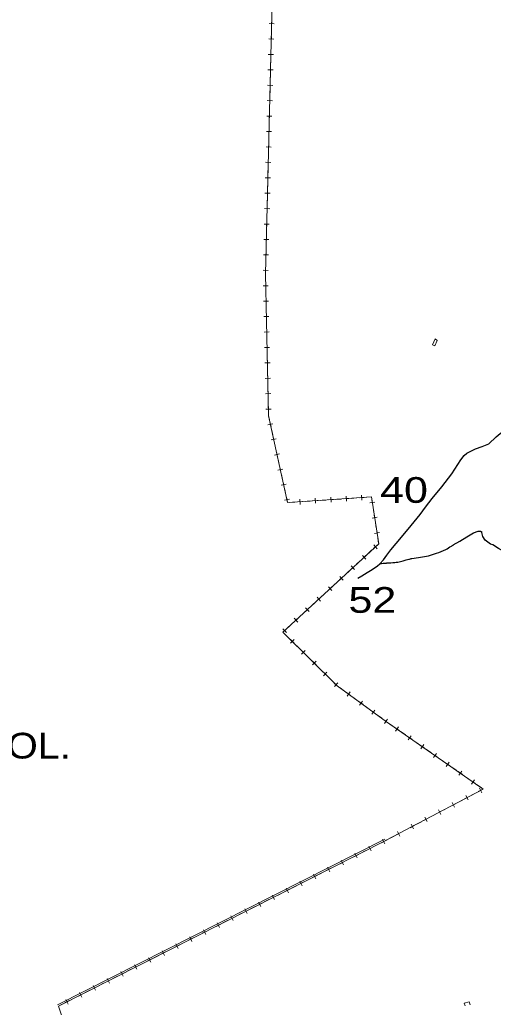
# Model space of a CAD drawing. Extents: x 476989 to 498418, y 4381813 to 4416555.
# Drawn here: x 483391 to 484310, y 4384840 to 4386760 of the extents above; entities that cross this region are included whole.
import ezdxf
from ezdxf.enums import TextEntityAlignment as Align

# ---------------------------------------------------------------- set-up
doc = ezdxf.new("R2010")
doc.units = 0
doc.header["$LTSCALE"] = 20
doc.linetypes.add('MEDIUM_DASHED', pattern=[4.5, 3, -1.5])
for name, color, linetype, lineweight in [('13', 7, 'Continuous', 13), ('34', 7, 'Continuous', 13), ('48', 7, 'MEDIUM_DASHED', 13), ('6', 7, 'Continuous', 25)]:
    doc.layers.add(name, color=color, linetype=linetype, lineweight=lineweight)

msp = doc.modelspace()

# ---------------------------------------------------------------- linework, layer by layer
at = {"layer": '34'}
for p, q in [((483880.12, 4386757.62), (483879.87, 4386747.63)), ((483874.99, 4386752.75), (483884.99, 4386752.5)), ((483879.75, 4386742.63), (483879.5, 4386732.63)), ((483874.25, 4386722.76), (483884.25, 4386722.51)), ((483879.38, 4386727.63), (483879.13, 4386717.64)), ((483879.01, 4386712.64), (483878.76, 4386702.64)), ((483873.52, 4386692.77), (483883.51, 4386692.52)), ((483878.27, 4386682.65), (483878.02, 4386672.65)), ((483878.64, 4386697.64), (483878.39, 4386687.64)), ((483872.78, 4386662.77), (483882.77, 4386662.53)), ((483877.9, 4386667.65), (483877.65, 4386657.65)), ((483877.53, 4386652.65), (483877.28, 4386642.66)), ((483872.04, 4386632.78), (483882.03, 4386632.54)), ((483876.79, 4386622.66), (483876.54, 4386612.67)), ((483877.16, 4386637.66), (483876.91, 4386627.66)), ((483871.3, 4386602.79), (483881.3, 4386602.55)), ((483876.42, 4386607.67), (483876.17, 4386597.67)), ((483876.05, 4386592.67), (483875.8, 4386582.68)), ((483870.56, 4386572.8), (483880.56, 4386572.56)), ((483875.68, 4386577.68), (483875.43, 4386567.68)), ((483874.94, 4386547.69), (483874.7, 4386537.69)), ((483875.31, 4386562.68), (483875.06, 4386552.69)), ((483869.82, 4386542.81), (483879.82, 4386542.56)), ((483874.57, 4386532.69), (483874.33, 4386522.69)), ((483869.08, 4386512.82), (483879.08, 4386512.57)), ((483874.2, 4386517.7), (483873.96, 4386507.7)), ((483873.46, 4386487.7), (483873.22, 4386477.71)), ((483873.83, 4386502.7), (483873.59, 4386492.7)), ((483868.34, 4386482.83), (483878.34, 4386482.58)), ((483873.09, 4386472.71), (483872.85, 4386462.71)), ((483867.6, 4386452.84), (483877.6, 4386452.59)), ((483872.72, 4386457.71), (483872.5, 4386448.65)), ((483872.35, 4386442.72), (483872.11, 4386432.72)), ((483872.5, 4386448.65), (483872.48, 4386447.72)), ((483866.86, 4386422.85), (483876.86, 4386422.6)), ((483871.62, 4386412.73), (483871.37, 4386402.73)), ((483871.99, 4386427.72), (483871.74, 4386417.73)), ((483866.12, 4386392.86), (483876.12, 4386392.61)), ((483871.25, 4386397.73), (483871, 4386387.74)), ((483870.88, 4386382.74), (483870.63, 4386372.74)), ((483865.39, 4386362.87), (483875.38, 4386362.62)), ((483870.51, 4386367.74), (483870.26, 4386357.74)), ((483869.77, 4386337.75), (483869.52, 4386327.75)), ((483870.14, 4386352.75), (483869.89, 4386342.75)), ((483864.65, 4386332.88), (483874.64, 4386332.63)), ((483869.4, 4386322.75), (483869.15, 4386312.76)), ((483863.91, 4386302.88), (483873.9, 4386302.64)), ((483869.03, 4386307.76), (483868.78, 4386297.76)), ((483868.29, 4386277.77), (483868.04, 4386267.77)), ((483868.66, 4386292.76), (483868.41, 4386282.77)), ((483863.17, 4386272.89), (483873.17, 4386272.65)), ((483868.07, 4386262.77), (483868.29, 4386252.78)), ((483863.51, 4386242.67), (483873.5, 4386242.89)), ((483868.4, 4386247.78), (483868.61, 4386237.78)), ((483868.72, 4386232.78), (483868.94, 4386222.78)), ((483864.16, 4386212.68), (483874.16, 4386212.89)), ((483869.05, 4386217.78), (483869.27, 4386207.79)), ((483869.37, 4386202.79), (483869.59, 4386192.79)), ((483864.81, 4386182.68), (483874.81, 4386182.9)), ((483869.7, 4386187.79), (483869.92, 4386177.79)), ((483870.03, 4386172.79), (483870.24, 4386162.8)), ((483865.46, 4386152.69), (483875.46, 4386152.91)), ((483870.35, 4386157.8), (483870.57, 4386147.8)), ((483870.68, 4386142.8), (483870.9, 4386132.8)), ((483866.11, 4386122.7), (483876.11, 4386122.91)), ((483871, 4386127.8), (483871.22, 4386117.81)), ((483871.33, 4386112.81), (483871.55, 4386102.81)), ((483866.77, 4386092.7), (483876.76, 4386092.92)), ((483871.66, 4386097.81), (483871.87, 4386087.81)), ((483871.98, 4386082.82), (483872.2, 4386072.82)), ((483872.31, 4386067.82), (483872.53, 4386057.82)), ((483867.42, 4386062.71), (483877.42, 4386062.93)), ((483872.63, 4386052.82), (483872.85, 4386042.82)), ((483868.07, 4386032.72), (483878.07, 4386032.94)), ((483872.96, 4386037.83), (483873.18, 4386027.83)), ((483873.29, 4386022.83), (483873.5, 4386012.83)), ((483873.61, 4386007.83), (483873.83, 4385997.84)), ((483868.72, 4386002.73), (483878.72, 4386002.94)), ((483872.79, 4385972.17), (483882.55, 4385974.3)), ((483876.6, 4385978.12), (483878.74, 4385968.35)), ((483879.81, 4385963.47), (483881.95, 4385953.7)), ((483879.2, 4385942.86), (483888.97, 4385945)), ((483883.02, 4385948.81), (483885.16, 4385939.04)), ((483886.23, 4385934.16), (483888.36, 4385924.39)), ((483885.62, 4385913.55), (483895.39, 4385915.69)), ((483889.43, 4385919.51), (483891.57, 4385909.74)), ((483892.64, 4385904.85), (483894.78, 4385895.09)), ((483892.03, 4385884.25), (483901.8, 4385886.39)), ((483895.85, 4385890.2), (483897.99, 4385880.43)), ((483899.06, 4385875.55), (483901.2, 4385865.78)), ((483898.45, 4385854.94), (483908.22, 4385857.08)), ((483902.27, 4385860.9), (483904.4, 4385851.13)), ((483905.47, 4385846.24), (483907.61, 4385836.47)), ((484055.17, 4385825.72), (484054.5, 4385835.7)), ((483904.87, 4385825.64), (483914.64, 4385827.77)), ((483908.68, 4385831.59), (483910.82, 4385821.82)), ((483915.15, 4385821.28), (483925.13, 4385821.95)), ((483930.12, 4385822.29), (483940.09, 4385822.96)), ((483935.44, 4385817.64), (483934.77, 4385827.62)), ((483945.08, 4385823.3), (483955.06, 4385823.97)), ((483960.05, 4385824.31), (483970.03, 4385824.98)), ((483965.37, 4385819.66), (483964.7, 4385829.64)), ((483975.01, 4385825.32), (483984.99, 4385825.99)), ((483989.98, 4385826.33), (483999.96, 4385827)), ((483995.31, 4385821.68), (483994.63, 4385831.66)), ((484004.95, 4385827.34), (484014.92, 4385828.01)), ((484019.91, 4385828.35), (484029.89, 4385829.02)), ((484025.24, 4385823.7), (484024.56, 4385833.68)), ((484034.88, 4385829.36), (484044.86, 4385830.03)), ((484049.84, 4385830.37), (484059.82, 4385831.04)), ((484070.7, 4385820.58), (484080.58, 4385822.1)), ((484074.88, 4385826.28), (484076.4, 4385816.39)), ((484077.16, 4385811.45), (484078.68, 4385801.57)), ((484079.44, 4385796.63), (484080.96, 4385786.74)), ((484075.26, 4385790.93), (484085.14, 4385792.45)), ((484081.72, 4385781.8), (484083.24, 4385771.92)), ((484079.82, 4385761.27), (484089.71, 4385762.79)), ((484084, 4385766.98), (484085.52, 4385757.09)), ((484085.27, 4385738.48), (484077.93, 4385731.69)), ((484078.2, 4385738.75), (484084.99, 4385731.41)), ((484086.28, 4385752.15), (484087.81, 4385742.27)), ((484074.26, 4385728.29), (484066.92, 4385721.5)), ((484052.23, 4385707.92), (484044.89, 4385701.13)), ((484063.24, 4385718.11), (484055.9, 4385711.32)), ((484056.18, 4385718.38), (484062.97, 4385711.04)), ((484030.21, 4385687.56), (484022.86, 4385680.77)), ((484041.22, 4385697.74), (484033.88, 4385690.95)), ((484034.15, 4385698.02), (484040.94, 4385690.67)), ((484008.18, 4385667.19), (484000.84, 4385660.4)), ((484019.19, 4385677.37), (484011.85, 4385670.58)), ((484012.13, 4385677.65), (484018.92, 4385670.31)), ((483986.15, 4385646.82), (483978.81, 4385640.03)), ((483997.17, 4385657), (483989.82, 4385650.21)), ((483990.1, 4385657.28), (483996.89, 4385649.94)), ((483964.13, 4385626.45), (483956.79, 4385619.66)), ((483975.14, 4385636.64), (483967.8, 4385629.85)), ((483968.07, 4385636.91), (483974.86, 4385629.57)), ((483942.1, 4385606.08), (483934.76, 4385599.29)), ((483953.11, 4385616.27), (483945.77, 4385609.48)), ((483946.05, 4385616.54), (483952.84, 4385609.2)), ((483920.08, 4385585.71), (483912.73, 4385578.93)), ((483931.09, 4385595.9), (483923.75, 4385589.11)), ((483924.02, 4385596.18), (483930.81, 4385588.83)), ((483902, 4385575.81), (483908.79, 4385568.47)), ((483905.82, 4385565.21), (483912.93, 4385558.18)), ((483916.48, 4385554.66), (483923.58, 4385547.62)), ((483916.51, 4385547.59), (483923.55, 4385554.69)), ((483927.14, 4385544.1), (483934.24, 4385537.06)), ((483937.79, 4385533.55), (483944.9, 4385526.51)), ((483937.83, 4385526.48), (483944.87, 4385533.58)), ((483948.45, 4385522.99), (483955.56, 4385515.95)), ((483959.11, 4385512.43), (483966.21, 4385505.4)), ((483959.14, 4385505.36), (483966.18, 4385512.47)), ((483969.77, 4385501.88), (483976.87, 4385494.84)), ((483980.42, 4385491.32), (483987.53, 4385484.29)), ((483980.46, 4385484.25), (483987.49, 4385491.36)), ((483991.08, 4385480.77), (483998.19, 4385473.73)), ((484001.77, 4385463.14), (484008.81, 4385470.25)), ((484013.14, 4385460.53), (484021.22, 4385454.63)), ((484025.26, 4385451.69), (484033.34, 4385445.8)), ((484026.35, 4385444.7), (484032.24, 4385452.78)), ((484037.38, 4385442.85), (484045.46, 4385436.96)), ((484049.5, 4385434.01), (484057.58, 4385428.12)), ((484050.59, 4385427.03), (484056.48, 4385435.11)), ((484061.62, 4385425.18), (484069.7, 4385419.28)), ((484073.74, 4385416.34), (484081.82, 4385410.45)), ((484074.83, 4385409.35), (484080.72, 4385417.43)), ((484085.86, 4385407.5), (484093.94, 4385401.61)), ((484097.98, 4385398.66), (484103, 4385395)), ((484099.07, 4385391.68), (484103.23, 4385397.38)), ((484103.23, 4385397.38), (484104.96, 4385399.76)), ((484107.1, 4385392.14), (484115.31, 4385386.42)), ((484119.41, 4385383.57), (484127.61, 4385377.85)), ((484120.65, 4385376.61), (484126.37, 4385384.81)), ((484131.72, 4385374.99), (484139.92, 4385369.27)), ((484144.02, 4385366.41), (484152.23, 4385360.7)), ((484145.27, 4385359.45), (484150.98, 4385367.66)), ((484156.33, 4385357.84), (484164.53, 4385352.12)), ((484168.64, 4385349.26), (484176.84, 4385343.55)), ((484169.88, 4385342.3), (484175.6, 4385350.51)), ((484180.94, 4385340.69), (484189.15, 4385334.97)), ((484193.25, 4385332.11), (484201.46, 4385326.4)), ((484194.49, 4385325.15), (484200.21, 4385333.36)), ((484205.56, 4385323.54), (484213.76, 4385317.82)), ((484219.11, 4385308), (484224.83, 4385316.21)), ((484217.86, 4385314.96), (484226.07, 4385309.24)), ((484230.17, 4385306.39), (484238.38, 4385300.67)), ((484242.48, 4385297.81), (484250.68, 4385292.09)), ((484243.72, 4385290.85), (484249.44, 4385299.05)), ((484254.79, 4385289.23), (484262.99, 4385283.52)), ((484267.09, 4385280.66), (484275.3, 4385274.94)), ((484268.34, 4385273.7), (484274.05, 4385281.9)), ((484279.4, 4385272.08), (484287.6, 4385266.37)), ((484290.24, 4385263.6), (484281.4, 4385258.92)), ((484283.48, 4385265.68), (484288.16, 4385256.84)), ((484250.46, 4385242.55), (484241.62, 4385237.88)), ((484263.72, 4385249.57), (484254.88, 4385244.89)), ((484256.96, 4385251.65), (484261.64, 4385242.81)), ((484276.98, 4385256.58), (484268.14, 4385251.91)), ((484210.69, 4385221.51), (484201.85, 4385216.83)), ((484203.93, 4385223.59), (484208.61, 4385214.75)), ((484223.95, 4385228.52), (484215.11, 4385223.85)), ((484237.21, 4385235.54), (484228.37, 4385230.86)), ((484230.45, 4385237.62), (484235.12, 4385228.78)), ((484184.17, 4385207.48), (484175.33, 4385202.8)), ((484177.41, 4385209.56), (484182.09, 4385200.72)), ((484197.43, 4385214.49), (484188.59, 4385209.82)), ((484124.38, 4385181.5), (484129.06, 4385172.66)), ((484144.4, 4385186.43), (484135.56, 4385181.75)), ((484157.65, 4385193.45), (484148.82, 4385188.77)), ((484150.9, 4385195.53), (484155.57, 4385186.69)), ((484170.91, 4385200.46), (484162.07, 4385195.79)), ((484100.12, 4385166.55), (483464.12, 4384844.55)), ((484100.12, 4385166.55), (483464.12, 4384844.55)), ((484102, 4385164), (483466, 4384842)), ((484102, 4385164), (484093.09, 4385159.49)), ((484099.81, 4385157.29), (484095.29, 4385166.21)), ((484102.72, 4385164.38), (484102, 4385164)), ((484102.72, 4385164.38), (484102, 4385164)), ((484104.62, 4385165.39), (484102.72, 4385164.38)), ((484117.88, 4385172.4), (484109.04, 4385167.72)), ((484131.14, 4385179.42), (484122.3, 4385174.74)), ((484061.87, 4385143.68), (484052.95, 4385139.17)), ((484075.25, 4385150.46), (484066.33, 4385145.94)), ((484073.05, 4385143.74), (484068.53, 4385152.66)), ((484088.63, 4385157.23), (484079.7, 4385152.71)), ((484019.54, 4385116.65), (484015.02, 4385125.57)), ((484035.11, 4385130.14), (484026.19, 4385125.62)), ((484048.5, 4385136.91), (484039.57, 4385132.39)), ((484046.29, 4385130.19), (484041.78, 4385139.11)), ((483994.98, 4385109.82), (483986.06, 4385105.3)), ((483992.78, 4385103.1), (483988.26, 4385112.02)), ((484008.36, 4385116.59), (483999.44, 4385112.07)), ((484021.74, 4385123.37), (484012.82, 4385118.85)), ((483954.85, 4385089.5), (483945.92, 4385084.98)), ((483968.23, 4385096.27), (483959.31, 4385091.76)), ((483966.03, 4385089.55), (483961.51, 4385098.47)), ((483981.6, 4385103.04), (483972.68, 4385098.53)), ((483914.72, 4385069.18), (483905.79, 4385064.66)), ((483912.51, 4385062.46), (483908, 4385071.38)), ((483928.09, 4385075.95), (483919.17, 4385071.43)), ((483941.47, 4385082.73), (483932.55, 4385078.21)), ((483939.27, 4385076.01), (483934.75, 4385084.93)), ((483874.58, 4385048.86), (483865.65, 4385044.34)), ((483887.96, 4385055.63), (483879.04, 4385051.12)), ((483885.76, 4385048.91), (483881.24, 4385057.84)), ((483901.33, 4385062.4), (483892.41, 4385057.89)), ((483834.45, 4385028.54), (483825.52, 4385024.02)), ((483832.24, 4385021.82), (483827.73, 4385030.74)), ((483847.82, 4385035.31), (483838.9, 4385030.79)), ((483861.2, 4385042.09), (483852.28, 4385037.57)), ((483859, 4385035.37), (483854.48, 4385044.29)), ((483807.69, 4385014.99), (483798.77, 4385010.48)), ((483805.49, 4385008.27), (483800.97, 4385017.2)), ((483821.06, 4385021.77), (483812.14, 4385017.25)), ((483751.98, 4384981.18), (483747.46, 4384990.1)), ((483767.55, 4384994.67), (483758.63, 4384990.16)), ((483780.93, 4385001.45), (483772.01, 4384996.93)), ((483778.73, 4384994.73), (483774.21, 4385003.65)), ((483794.31, 4385008.22), (483785.39, 4385003.7)), ((483727.42, 4384974.36), (483718.5, 4384969.84)), ((483725.22, 4384967.64), (483720.7, 4384976.56)), ((483740.8, 4384981.13), (483731.87, 4384976.61)), ((483754.18, 4384987.9), (483745.26, 4384983.38)), ((483687.28, 4384954.03), (483678.36, 4384949.52)), ((483700.67, 4384960.81), (483691.74, 4384956.29)), ((483698.46, 4384954.09), (483693.95, 4384963.01)), ((483714.04, 4384967.58), (483705.12, 4384963.06)), ((483647.15, 4384933.72), (483638.23, 4384929.2)), ((483644.95, 4384927), (483640.43, 4384935.92)), ((483660.53, 4384940.49), (483651.61, 4384935.97)), ((483673.91, 4384947.26), (483664.99, 4384942.75)), ((483671.71, 4384940.54), (483667.19, 4384949.46)), ((483607.01, 4384913.39), (483598.09, 4384908.88)), ((483620.4, 4384920.17), (483611.48, 4384915.65)), ((483618.19, 4384913.45), (483613.68, 4384922.37)), ((483633.77, 4384926.94), (483624.85, 4384922.42)), ((483564.68, 4384886.36), (483560.17, 4384895.28)), ((483580.26, 4384899.85), (483571.34, 4384895.33)), ((483593.64, 4384906.62), (483584.72, 4384902.11)), ((483591.44, 4384899.9), (483586.92, 4384908.83)), ((483540.13, 4384879.53), (483531.21, 4384875.01)), ((483537.93, 4384872.81), (483533.41, 4384881.73)), ((483553.5, 4384886.3), (483544.58, 4384881.78)), ((483566.88, 4384893.08), (483557.96, 4384888.56)), ((483499.99, 4384859.21), (483491.07, 4384854.69)), ((483513.37, 4384865.98), (483504.45, 4384861.47)), ((483511.17, 4384859.26), (483506.65, 4384868.19)), ((483526.75, 4384872.75), (483517.82, 4384868.24)), ((483473.23, 4384845.66), (483466, 4384842)), ((483466, 4384842), (483699.09, 4384136.76)), ((483486.62, 4384852.44), (483477.69, 4384847.92)), ((483484.41, 4384845.72), (483479.9, 4384854.64))]:
    msp.add_line(p, q, dxfattribs=at)
for points in [[(484108, 4387807), (483853, 4387811), (483851, 4387468), (483887, 4387037), (483872.5, 4386448.65)], [(483872.5, 4386448.65), (483868, 4386266), (483874, 4385990), (483911, 4385821), (484074, 4385832), (484088, 4385741), (483902, 4385569), (484007, 4385465), (484103, 4385395), (484103.22, 4385394.84)], [(483873.94, 4385992.84), (483874, 4385990), (483875.53, 4385983)], [(484064.81, 4385831.38), (484074, 4385832), (484074.12, 4385831.22)], [(483909.06, 4385575.53), (483902, 4385569), (483902.27, 4385568.73)], [(484001.74, 4385470.21), (484007, 4385465), (484009.1, 4385463.47)], [(484103.22, 4385394.84), (484291, 4385264), (484102.72, 4385164.38)]]:
    msp.add_lwpolyline(points, dxfattribs=at)
at = {"layer": '48'}
msp.add_lwpolyline([(484201.31, 4386136.21), (484196.74, 4386125.7), (484192.21, 4386127.89), (484197.76, 4386139.26)], close=True, dxfattribs=at)
msp.add_lwpolyline([(484265.71, 4384844.4), (484263.66, 4384850.43), (484253.69, 4384847.41), (484255.71, 4384842.64)], dxfattribs=at)
at = {"layer": '6'}
for points in [[(484103.92, 4385718.57), (484111.72, 4385728.95), (484132.39, 4385753.72), (484150.74, 4385776.42), (484168.25, 4385798.21), (484178.85, 4385811.99), (484192.12, 4385829), (484210.84, 4385851.58), (484229.9, 4385876.92), (484247.2, 4385904.12), (484254.19, 4385912.82), (484258.83, 4385917.22), (484264.2, 4385920.12), (484276.08, 4385925.76), (484289.25, 4385930.22), (484301.63, 4385935.61), (484316.4, 4385948.98), (484330.76, 4385961.22)], [(484232.71, 4385738.67), (484245.82, 4385746.08), (484258.89, 4385754.17), (484271.96, 4385762.25), (484281.3, 4385765.36), (484285.65, 4385765.36), (484288.73, 4385763.8)], [(484369.87, 4385737.2), (484364.99, 4385736.16), (484360, 4385734.88), (484353.19, 4385731.05), (484349.68, 4385726.82), (484342.51, 4385723.3), (484339.54, 4385722.65), (484335.38, 4385723.47), (484320.6, 4385731.82), (484309.66, 4385739), (484305.07, 4385740.5), (484294.96, 4385748), (484290.13, 4385755.39), (484288.41, 4385763.09), (484288.39, 4385763.58)], [(484047.21, 4385673.91), (484055.33, 4385678.48), (484065.21, 4385684.94), (484075.49, 4385691.28), (484085.83, 4385698.04), (484090.13, 4385702.27), (484097.28, 4385709.73), (484103.92, 4385718.57)]]:
    msp.add_lwpolyline(points, dxfattribs=at)
for points in [[(484103.89, 4385703.63), (484119.2, 4385704.68), (484124.8, 4385705.49), (484146.59, 4385710.97), (484152.48, 4385712.37), (484169.37, 4385715.15), (484184.78, 4385717.66), (484200.05, 4385722.45), (484218.09, 4385729.84), (484229.06, 4385736.5), (484233.74, 4385739.28)], [(484090.86, 4385702.36), (484101.98, 4385703.5), (484103.89, 4385703.63)]]:
    msp.add_spline(points, degree=3, dxfattribs=at)

# ---------------------------------------------------------------- texts
at = {"layer": '13', "width": 1.25}
for s, p in [('40', (484137.13, 4385820.61)), ('52', (484075.65, 4385606.73))]:
    msp.add_text(s, height=50, dxfattribs=at).set_placement(p, align=Align.CENTER)
at = {"layer": '13', "width": 1.15}
msp.add_text("39- CAMÍ DE SES OLLERIES AL PUIG DE SON SEGUÍ/CAMÍ DES COSTER D'EN TOFOL.", height=50, dxfattribs=at).set_placement((480330.43, 4385323.38))

doc.saveas('drawing.dxf')
